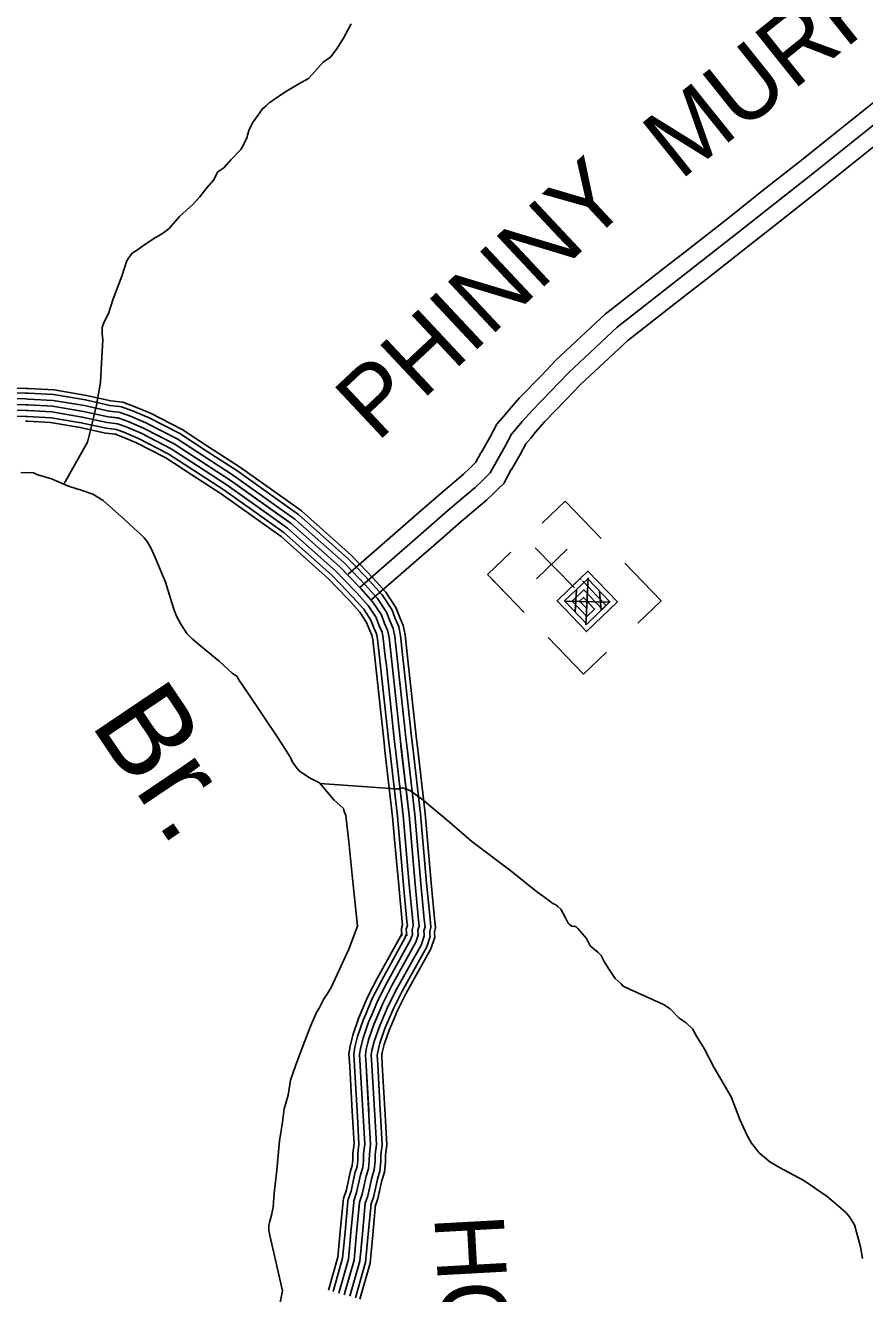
# Model space of a CAD drawing. Extents: x 1551132 to 1791609, y 378168 to 563823.
# Drawn here: x 1659703 to 1664184, y 426270 to 433041 of the extents above; entities that cross this region are included whole.
import ezdxf

# ---------------------------------------------------------------- set-up
doc = ezdxf.new("R2010")
doc.units = 0
for name, color, linetype in [('DESIGN - DRAINAGE - Bridges and Cross Drains Size Text', 7, 'Continuous'), ('DESIGN - ROW - Right-of-Way and Easement Labels', 7, 'Continuous'), ('DESIGN - TRANSPORTATION - Text', 7, 'Continuous'), ('DESIGN - UTILITIES - Cable (Underground) with Text', 7, 'Continuous'), ('SURVEY - CONTOURS - Index with Text', 7, 'Continuous'), ('SURVEY - PROPERTY - Owners', 7, 'Continuous')]:
    doc.layers.add(name, color=color, linetype=linetype)

msp = doc.modelspace()

# ---------------------------------------------------------------- linework, layer by layer
at = {"layer": 'DESIGN - TRANSPORTATION - Text'}
for points in [[(1659909.588, 430590.846), (1660034.993, 430815.902), (1660052.951, 430887.929), (1660083.842, 431013.89), (1660104.7, 431133.918), (1660109.459, 431238.038), (1660116.358, 431362.166), (1660112.592, 431394.242), (1660112.842, 431428.284), (1660123.025, 431454.252), (1660147.349, 431502.153), (1660169.866, 431576.105), (1660218.74, 431701.942), (1660235.089, 431751.901), (1660243.281, 431779.885), (1660253.405, 431797.844), (1660273.588, 431825.745), (1660301.688, 431843.57), (1660341.853, 431871.338), (1660392.052, 431905.03), (1660436.193, 431930.764), (1660470.35, 431956.565), (1660526.758, 432020.267), (1660599.164, 432085.86), (1660633.405, 432123.67), (1660671.729, 432173.479), (1660708.003, 432215.289), (1660730.295, 432259.198), (1660762.427, 432281.007), (1660802.71, 432324.783), (1660853.05, 432378.518), (1660867.208, 432402.452), (1660885.466, 432440.378), (1660895.749, 432480.362), (1660916.024, 432520.28), (1660944.281, 432560.14), (1660968.522, 432596.024), (1660988.622, 432611.908), (1661004.722, 432627.816), (1661026.796, 432641.683), (1661089.053, 432685.318), (1661163.301, 432728.861), (1661215.45, 432756.545), (1661263.807, 432812.288), (1661291.998, 432842.13), (1661334.189, 432873.89), (1661364.447, 432913.732), (1661400.846, 432973.567), (1661443.362, 433049.378)], [(1659678.535, 430653.997), (1659746.45, 430651.522), (1659770.358, 430641.339), (1659842.131, 430620.813), (1659933.746, 430580.12), (1660007.502, 430557.578), (1660063.318, 430539.161), (1660119.008, 430504.727), (1660232.155, 430403.799), (1660283.754, 430355.365), (1660315.512, 430327.106), (1660337.328, 430304.922), (1660353.169, 430284.788), (1660374.885, 430248.579), (1660396.51, 430200.361), (1660451.483, 430067.791), (1660494.432, 429929.295), (1660510.107, 429887.128), (1660531.79, 429846.918), (1660553.531, 429814.717), (1660565.372, 429794.608), (1660593.138, 429766.374), (1660648.745, 429719.923), (1660738.126, 429647.196), (1660785.75, 429602.804), (1660807.583, 429582.62), (1660833.424, 429564.419), (1660843.282, 429546.319), (1660888.756, 429479.909), (1661052.81, 429236.419), (1661117.984, 429131.816), (1661129.792, 429107.707), (1661149.583, 429081.532), (1661165.416, 429061.39), (1661183.316, 429049.248), (1661223.081, 429022.939), (1661272.838, 428996.555), (1661352.078, 428903.869), (1661381.861, 428877.627), (1661401.71, 428859.459), (1661405.585, 428843.409), (1661413.435, 428823.325), (1661430.393, 428683.005), (1661447.067, 428504.633)], [(1661276.072, 428992.771), (1661679.287, 428965.879), (1661697.27, 428965.754), (1661717.278, 428969.621), (1661733.228, 428965.504), (1661735.228, 428965.487), (1661759.127, 428955.312), (1661824.709, 428906.786), (1661967.697, 428787.624), (1662086.828, 428684.647), (1662295.464, 428526.968), (1662432.528, 428417.865), (1662496.126, 428371.356), (1662519.967, 428353.163), (1662535.9, 428345.038), (1662545.825, 428336.963), (1662561.708, 428322.829), (1662587.341, 428276.586), (1662601.124, 428248.452), (1662607.073, 428242.402), (1662620.99, 428232.285), (1662630.965, 428230.219), (1662634.973, 428232.194), (1662642.931, 428228.127), (1662652.864, 428220.052), (1662664.747, 428205.951), (1662698.421, 428165.659), (1662718.121, 428127.466), (1662728.054, 428119.382), (1662739.97, 428109.29), (1662759.828, 428093.123), (1662777.678, 428074.973), (1662793.427, 428042.822), (1662817.143, 428006.604), (1662852.709, 427952.278), (1662884.475, 427924.019), (1662894.375, 427911.935), (1662928.224, 427895.677), (1663109.445, 427814.3), (1663145.236, 427790.016), (1663192.834, 427741.614), (1663230.6, 427715.314), (1663264.333, 427683.038), (1663286.032, 427644.829), (1663327.506, 427578.443), (1663378.73, 427479.949), (1663471.478, 427321.078), (1663516.552, 427200.592), (1663555.884, 427114.198), (1663579.567, 427073.972), (1663621.141, 427021.612), (1663676.731, 426973.153), (1663728.463, 426942.752), (1663859.827, 426873.742), (1663983.082, 426788.765), (1664040.672, 426740.289), (1664084.346, 426701.938), (1664102.163, 426679.779), (1664129.829, 426637.528), (1664160.936, 426519.141), (1664172.111, 426457.29)], [(1661447.067, 428504.633), (1661476.008, 428231.776), (1661429.268, 428108.381), (1661335.878, 427904.734), (1661315.662, 427872.833), (1661295.454, 427840.924), (1661271.138, 427795.031), (1661256.98, 427771.097), (1661226.497, 427701.204), (1661183.74, 427591.343), (1661144.999, 427485.465), (1661118.475, 427409.538), (1661105.9, 427329.511), (1661085.4, 427257.551), (1661076.875, 427185.507), (1661060.167, 427085.471), (1661045.043, 426929.359), (1661032.16, 426807.272), (1661025.61, 426731.203), (1661017.31, 426689.202), (1661009.085, 426657.218), (1661002.935, 426635.226), (1661002.744, 426609.192), (1661008.535, 426581.108), (1661024.001, 426510.898), (1661053.067, 426386.519), (1661076.308, 426284.833)], [(1661076.308, 426284.833), (1660983.377, 425821.596), (1660931.436, 425683.818), (1660933.37, 425673.792), (1660948.894, 425601.565), (1660986.302, 425511.155), (1660990.91, 425500.588)]]:
    msp.add_lwpolyline(points, dxfattribs=at)
at = {"layer": 'DESIGN - UTILITIES - Cable (Underground) with Text'}
for p, q in [((1662462.01, 430383.033), (1662585.472, 430501.483)), ((1662777.58, 430301.289), (1662585.472, 430501.483)), ((1662171.011, 430109.835), (1662294.465, 430228.243)), ((1662596.209, 430244.655), (1662431.614, 430086.739)), ((1663096.619, 429968.617), (1662903.545, 430169.952)), ((1662171.011, 430109.835), (1662269.743, 430006.922)), ((1662188.735, 430091.31), (1662366.234, 429906.341)), ((1662973.157, 429850.209), (1663096.619, 429968.617)), ((1662493.967, 429773.112), (1662682.199, 429576.927)), ((1662682.199, 429576.927), (1662805.654, 429695.376))]:
    msp.add_line(p, q, dxfattribs=at)
for points in [[(1662424.97, 430252.044), (1662633.969, 430037.776)], [(1662620.678, 430051.409), (1662623.711, 430048.375), (1662705.992, 430127.358), (1662863.907, 429962.714), (1662699.304, 429804.84), (1662541.397, 429969.401), (1662664.851, 430087.842), (1662670.268, 430082.209)], [(1662677.176, 430075.001), (1662803.009, 429943.797), (1662700.145, 429845.105), (1662581.696, 429968.56), (1662705.159, 430087.009), (1662823.6, 429963.596), (1662782.468, 429924.08), (1662683.777, 430026.952), (1662622.045, 429967.769), (1662700.978, 429885.446), (1662742.119, 429924.913), (1662682.936, 429986.644), (1662662.345, 429966.894), (1662701.811, 429925.796)], [(1662645.586, 430028.401), (1662638.762, 429910.745)], [(1662706.875, 430091.451), (1662695.129, 429840.88)], [(1662582.179, 429967.551), (1662818.675, 429961.571)], [(1662768.6, 430018.195), (1662776.393, 429918.805)]]:
    msp.add_lwpolyline(points, dxfattribs=at)
at = {"layer": 'SURVEY - CONTOURS - Index with Text'}
for points in [[(1659705.093, 431102.192), (1659445.732, 431104.676), (1659199.663, 431090.375)], [(1659704.851, 431077.475), (1659446.332, 431079.95), (1659201.105, 431065.699)], [(1659704.56, 431046.474), (1659447.082, 431048.941), (1659202.896, 431034.757)], [(1660201.673, 430975.939), (1660149.991, 430981.806), (1660019.127, 431010.923), (1659850.981, 431038.957), (1659718.693, 431046.341), (1659704.535, 431046.474)], [(1660205.173, 431006.748), (1660155.124, 431012.424), (1660025.052, 431041.366), (1659854.406, 431069.817), (1659719.701, 431077.333), (1659704.818, 431077.475)], [(1660207.956, 431031.307), (1660159.207, 431036.833), (1660029.769, 431065.633), (1659857.131, 431094.417), (1659720.509, 431102.042), (1659705.051, 431102.192)], [(1659704.26, 431015.473), (1659447.832, 431017.932), (1659204.696, 431003.806)], [(1659703.96, 430984.473), (1659448.582, 430986.922), (1659206.496, 430972.855)], [(1661406.009, 426264.45), (1661458.199, 426448.738), (1661471.608, 426592.8), (1661487.224, 426758.871), (1661501.632, 426800.789), (1661522.556, 426896.716), (1661534.94, 426936.651), (1661539.348, 426978.66), (1661539.706, 427014.703), (1661546.206, 427066.712), (1661537.723, 427220.992), (1661522.34, 427487.49), (1661518.907, 427545.6), (1661523.182, 427573.592), (1661535.682, 427625.544), (1661564.473, 427707.371), (1661611.538, 427819.074), (1661660.454, 427914.726), (1661788.659, 428145.808), (1661801.026, 428183.742), (1661799.276, 428209.793), (1661805.492, 428231.76), (1661801.809, 428263.836), (1661783.701, 428456.266), (1661751.319, 428825.059), (1661705.203, 429220.011), (1661661.205, 429626.963), (1661644.647, 429773.317), (1661637.022, 429811.443), (1661621.389, 429847.635), (1661603.848, 429893.862), (1661558.541, 429962.388), (1661495.259, 430033.082), (1661382.461, 430150.318), (1661122.834, 430381.099), (1660797.25, 430612.513), (1660497.299, 430807.635), (1660334.186, 430891.295), (1660252.572, 430926.121), (1660202.773, 430944.622), (1660144.866, 430951.189), (1660013.211, 430980.481), (1659847.556, 431008.098), (1659717.684, 431015.348), (1659447.832, 431017.932)], [(1660194.69, 430914.338), (1660139.741, 430920.571), (1660007.294, 430950.038), (1659844.131, 430977.239), (1659716.676, 430984.356), (1659703.951, 430984.473)], [(1660198.181, 430945.138), (1660144.866, 430951.189), (1660013.211, 430980.481), (1659847.556, 431008.098), (1659717.684, 431015.348), (1659704.243, 431015.473)], [(1660656.854, 430740.817), (1660512.866, 430834.494), (1660347.361, 430919.38), (1660264.055, 430954.922), (1660210.031, 430974.998), (1660201.673, 430975.948)], [(1660673.762, 430766.809), (1660528.432, 430861.345), (1660360.536, 430947.464), (1660275.546, 430983.731), (1660217.289, 431005.373), (1660205.181, 431006.748)], [(1660687.236, 430787.526), (1660540.84, 430882.762), (1660371.036, 430969.856), (1660284.704, 431006.69), (1660223.072, 431029.591), (1660207.981, 431031.307)], [(1659703.668, 430953.472), (1659449.332, 430955.913), (1659208.288, 430941.913)], [(1660188.29, 430857.978), (1660130.358, 430864.553), (1659996.461, 430894.345), (1659837.873, 430920.779), (1659714.834, 430927.654), (1659703.426, 430927.754)], [(1660191.19, 430883.529), (1660134.608, 430889.954), (1660001.369, 430919.596), (1659840.706, 430946.38), (1659715.668, 430953.363), (1659703.668, 430953.472)], [(1660623.055, 430688.849), (1660481.733, 430780.776), (1660321.012, 430863.211), (1660241.089, 430897.321), (1660195.515, 430914.246), (1660194.656, 430914.346)], [(1660639.954, 430714.833), (1660497.299, 430807.635), (1660334.186, 430891.295), (1660252.572, 430926.121), (1660202.773, 430944.622), (1660198.165, 430945.147)], [(1660592.122, 430641.306), (1660453.25, 430731.641), (1660296.912, 430811.827), (1660220.072, 430844.619), (1660182.24, 430858.678)], [(1660606.147, 430662.856), (1660466.167, 430753.925), (1660307.837, 430835.127), (1660229.597, 430868.511), (1660188.257, 430883.87)], [(1661102.06, 430502.252), (1660846.033, 430684.232), (1660687.22, 430787.543)], [(1661051.828, 430431.567), (1660797.25, 430612.513), (1660639.938, 430714.849)], [(1661069.786, 430456.834), (1660814.692, 430638.156), (1660656.837, 430740.833)], [(1661087.744, 430482.102), (1660832.125, 430663.79), (1660673.745, 430766.826)], [(1661001.012, 430360.065), (1660747.91, 430539.97), (1660592.105, 430641.322)], [(1661015.912, 430381.032), (1660762.376, 430561.237), (1660606.13, 430662.873)], [(1661033.87, 430406.3), (1660779.809, 430586.871), (1660623.038, 430688.865)], [(1661490.351, 430163.252), (1661442.602, 430212.887), (1661176.916, 430449.051), (1661102.043, 430502.261)], [(1661427.869, 430103.125), (1661382.461, 430150.318), (1661122.834, 430381.099), (1661051.811, 430431.575)], [(1661450.21, 430124.618), (1661403.961, 430172.686), (1661142.167, 430405.391), (1661069.769, 430456.843)], [(1661472.543, 430146.118), (1661425.46, 430195.053), (1661161.5, 430429.684), (1661087.727, 430482.118)], [(1661383.195, 430060.133), (1661339.462, 430105.584), (1661084.169, 430332.515), (1661015.895, 430381.032)], [(1661405.528, 430081.633), (1661360.962, 430127.951), (1661103.501, 430356.807), (1661033.853, 430406.308)], [(1661364.662, 430042.307), (1661321.63, 430087.033), (1661068.127, 430312.364), (1661000.996, 430360.074)], [(1661741.828, 429685.673), (1661730.395, 429786.717), (1661720.253, 429837.427), (1661701.771, 429880.228), (1661681.496, 429933.646), (1661627.381, 430015.507), (1661558.824, 430092.083), (1661490.351, 430163.26)], [(1661655.663, 429675.923), (1661644.647, 429773.317), (1661637.022, 429811.443), (1661621.389, 429847.635), (1661603.848, 429893.862), (1661558.541, 429962.388), (1661495.259, 430033.082), (1661427.86, 430103.134)], [(1661686.462, 429679.406), (1661675.304, 429778.109), (1661666.78, 429820.735), (1661650.122, 429859.286), (1661631.606, 429908.087), (1661583.148, 429981.381), (1661517.983, 430054.174), (1661450.202, 430124.626)], [(1661717.27, 429682.889), (1661705.954, 429782.9), (1661696.529, 429830.018), (1661678.863, 429870.936), (1661659.363, 429922.304), (1661607.756, 430000.364), (1661540.708, 430075.266), (1661472.534, 430146.118)], [(1661568.507, 429666.064), (1661557.907, 429759.758), (1661552.824, 429785.159), (1661540.083, 429814.668), (1661525.3, 429853.619), (1661488.909, 429908.662), (1661430.96, 429973.397), (1661364.654, 430042.315)], [(1661594.056, 429668.956), (1661583.34, 429763.733), (1661577.515, 429792.867), (1661563.915, 429824.335), (1661548.332, 429865.419), (1661509.325, 429924.412), (1661449.81, 429990.897), (1661383.186, 430060.149)], [(1661624.864, 429672.439), (1661613.989, 429768.525), (1661607.264, 429802.151), (1661592.656, 429835.985), (1661576.09, 429879.636), (1661533.933, 429943.396), (1661472.534, 430011.99), (1661405.519, 430081.641)], [(1661622.88, 429168.718), (1661618.039, 429210.21), (1661574.023, 429617.313), (1661568.507, 429666.081)], [(1661648.421, 429171.693), (1661643.597, 429213.085), (1661599.581, 429620.146), (1661594.056, 429668.964)], [(1661679.212, 429175.293), (1661674.396, 429216.544), (1661630.397, 429623.555), (1661624.864, 429672.456)], [(1661710.003, 429178.885), (1661705.203, 429220.011), (1661661.205, 429626.963), (1661655.663, 429675.939)], [(1661740.794, 429182.476), (1661736.011, 429223.477), (1661692.012, 429630.371), (1661686.462, 429679.423)], [(1661771.585, 429186.076), (1661766.81, 429226.936), (1661722.828, 429633.78), (1661717.27, 429682.914)], [(1661796.135, 429188.935), (1661791.376, 429229.703), (1661747.394, 429636.497), (1661741.828, 429685.69)], [(1661676.512, 428674.171), (1661664.054, 428816.133), (1661622.88, 429168.726)], [(1661702.137, 428676.421), (1661689.637, 428818.75), (1661648.421, 429171.709)], [(1661733.011, 428679.138), (1661720.478, 428821.9), (1661679.212, 429175.309)], [(1661763.893, 428681.847), (1661751.319, 428825.059), (1661710.003, 429178.901)], [(1661794.776, 428684.555), (1661782.16, 428828.217), (1661740.794, 429182.493)], [(1661825.65, 428687.272), (1661813.001, 428831.367), (1661771.585, 429186.093)], [(1661850.275, 428689.43), (1661837.592, 428833.884), (1661796.135, 429188.96)], [(1661713.444, 428178.825), (1661710.744, 428219.068), (1661716.369, 428238.968), (1661714.561, 428254.719), (1661696.345, 428448.324), (1661676.512, 428674.188)], [(1661739.102, 428180.55), (1661736.694, 428216.351), (1661742.502, 428236.86), (1661740.144, 428257.394), (1661721.961, 428450.649), (1661702.137, 428676.438)], [(1661770.026, 428182.625), (1661767.985, 428213.068), (1661773.993, 428234.31), (1661770.976, 428260.611), (1661752.827, 428453.457), (1661733.011, 428679.155)], [(1661800.959, 428184.7), (1661799.276, 428209.793), (1661805.492, 428231.76), (1661801.809, 428263.836), (1661783.701, 428456.266), (1661763.893, 428681.863)], [(1661831.892, 428186.775), (1661830.567, 428206.518), (1661836.991, 428229.21), (1661832.642, 428267.061), (1661814.575, 428459.074), (1661794.776, 428684.572)], [(1661862.816, 428188.85), (1661861.858, 428203.234), (1661868.482, 428226.66), (1661863.474, 428270.278), (1661845.441, 428461.883), (1661825.65, 428687.288)], [(1661887.482, 428190.509), (1661886.799, 428200.617), (1661893.598, 428224.635), (1661888.057, 428272.844), (1661870.057, 428464.124), (1661850.275, 428689.447)], [(1661496.758, 427772.556), (1661531.965, 427856.125), (1661583.031, 427955.986), (1661707.878, 428181), (1661712.353, 428194.742)], [(1661520.457, 427762.572), (1661555.298, 427845.266), (1661605.73, 427943.894), (1661731.561, 428170.683), (1661738.352, 428191.517)], [(1661549.023, 427750.53), (1661583.414, 427832.166), (1661633.096, 427929.31), (1661760.11, 428158.25), (1661769.685, 428187.634)], [(1661577.589, 427738.497), (1661611.538, 427819.074), (1661660.454, 427914.726), (1661788.659, 428145.808), (1661801.026, 428183.742), (1661800.959, 428184.717)], [(1661606.155, 427726.463), (1661639.663, 427805.982), (1661687.811, 427900.143), (1661817.209, 428133.366), (1661832.367, 428179.85), (1661831.883, 428186.834)], [(1661634.721, 427714.421), (1661667.779, 427792.882), (1661715.177, 427885.559), (1661845.758, 428120.932), (1661863.699, 428175.967), (1661862.816, 428188.95)], [(1661657.504, 427704.821), (1661690.203, 427782.448), (1661736.994, 427873.934), (1661868.524, 428111.015), (1661888.69, 428172.867), (1661887.474, 428190.634)], [(1661448.567, 427243.325), (1661434.776, 427482.373), (1661430.801, 427549.683), (1661437.034, 427590.501), (1661451.45, 427650.428), (1661482.616, 427738.988), (1661496.766, 427772.581)], [(1661474.241, 427244.8), (1661460.45, 427483.873), (1661456.633, 427548.483), (1661462.292, 427585.543), (1661476.141, 427643.136), (1661506.616, 427729.721), (1661520.465, 427762.597)], [(1661505.19, 427246.592), (1661491.391, 427485.682), (1661487.766, 427547.042), (1661492.733, 427579.568), (1661505.916, 427634.336), (1661535.54, 427718.546), (1661549.031, 427750.555)], [(1661536.14, 427248.376), (1661522.34, 427487.49), (1661518.907, 427545.6), (1661523.182, 427573.592), (1661535.682, 427625.544), (1661564.473, 427707.371), (1661577.597, 427738.513)], [(1661567.089, 427250.159), (1661553.289, 427489.299), (1661550.048, 427544.158), (1661553.631, 427567.617), (1661565.448, 427616.752), (1661593.405, 427696.196), (1661606.163, 427726.471)], [(1661598.038, 427251.951), (1661584.23, 427491.107), (1661581.18, 427542.717), (1661584.072, 427561.642), (1661595.222, 427607.952), (1661622.33, 427685.02), (1661634.729, 427714.429)], [(1661622.713, 427253.376), (1661608.905, 427492.549), (1661606.013, 427541.567), (1661608.346, 427556.875), (1661618.955, 427600.943), (1661645.396, 427676.112), (1661657.504, 427704.838)], [(1661517.74, 426752.296), (1661531.531, 426792.422), (1661552.556, 426888.808), (1661565.447, 426930.384), (1661570.33, 426976.885), (1661570.689, 427012.619), (1661577.314, 427065.629), (1661568.672, 427222.733), (1661567.089, 427250.184)], [(1661548.264, 426745.721), (1661561.439, 426784.047), (1661582.563, 426880.899), (1661595.963, 426924.117), (1661601.313, 426975.11), (1661601.663, 427010.536), (1661608.413, 427064.554), (1661599.622, 427224.483), (1661598.038, 427251.967)], [(1661572.597, 426740.471), (1661585.28, 426777.372), (1661606.488, 426874.591), (1661620.288, 426919.117), (1661626.021, 426973.693), (1661626.371, 427008.878), (1661633.221, 427063.696), (1661624.304, 427225.875), (1661622.713, 427253.392)], [(1661399.609, 426764.029), (1661400.868, 426777.48), (1661417.017, 426824.473), (1661437.658, 426919.092), (1661448.608, 426954.393), (1661451.675, 426983.685), (1661452.05, 427020.595), (1661458.191, 427069.771), (1661450.15, 427216.05), (1661448.575, 427243.334)], [(1661425.209, 426761.629), (1661426.184, 426772.021), (1661441.825, 426817.531), (1661462.55, 426912.533), (1661473.916, 426949.184), (1661477.383, 426982.21), (1661477.749, 427018.87), (1661483.999, 427068.871), (1661475.824, 427217.5), (1661474.241, 427244.817)], [(1661456.075, 426758.738), (1661456.708, 426765.446), (1661471.733, 426809.156), (1661492.557, 426904.625), (1661504.432, 426942.918), (1661508.365, 426980.435), (1661508.724, 427016.786), (1661515.098, 427067.796), (1661506.774, 427219.25), (1661505.19, 427246.6)], [(1661486.941, 426755.846), (1661487.224, 426758.871), (1661501.632, 426800.789), (1661522.556, 426896.716), (1661534.94, 426936.651), (1661539.348, 426978.66), (1661539.706, 427014.703), (1661546.206, 427066.712), (1661537.723, 427220.992), (1661536.14, 427248.392)], [(1661321.611, 426288.35), (1661371.61, 426464.888), (1661384.276, 426600.967), (1661399.609, 426764.071)], [(1661346.36, 426281.342), (1661396.993, 426460.155), (1661409.876, 426598.575), (1661425.217, 426761.671)], [(1661376.185, 426272.9), (1661427.6, 426454.446), (1661440.742, 426595.692), (1661456.075, 426758.763)], [(1661406.009, 426264.45), (1661458.199, 426448.738), (1661471.608, 426592.8), (1661486.941, 426755.863)], [(1661435.833, 426255.999), (1661488.799, 426443.029), (1661502.473, 426589.908), (1661517.807, 426752.963)], [(1661465.657, 426247.558), (1661519.406, 426437.321), (1661533.339, 426587.025), (1661548.664, 426750.054)], [(1661489.44, 426240.816), (1661543.806, 426432.771), (1661557.947, 426584.725), (1661573.272, 426747.746)]]:
    msp.add_lwpolyline(points, dxfattribs=at)
at = {"layer": 'SURVEY - PROPERTY - Owners'}
for points in [[(1661488.409, 430040.207), (1661971.231, 430461.102), (1662104.27, 430573.98), (1662142.411, 430609.939), (1662161.835, 430629.365), (1662184.993, 430651.307), (1662217.584, 430713.075), (1662264.858, 430794.919), (1662298.965, 430858.487), (1662331.323, 430896.23), (1662355.597, 430926.039), (1662410.179, 430987.599), (1662602.033, 431186.021), (1662862.294, 431429.861), (1663158.429, 431661.334), (1663510.954, 431936.324), (1663913.887, 432254.891), (1664697.669, 432882.233)], [(1661426.452, 430111.284), (1661803.343, 430439.834), (1661909.749, 430532.595), (1662041.388, 430644.282), (1662076.72, 430677.599), (1662096.062, 430696.941), (1662108.853, 430709.067), (1662135.027, 430758.66), (1662137.611, 430763.143), (1662182.476, 430840.803), (1662220.717, 430912.089), (1662258.966, 430956.698), (1662283.732, 430987.116), (1662340.981, 431051.684), (1662457.978, 431172.687), (1662535.868, 431253.239), (1662800.904, 431501.554), (1662830.728, 431524.872), (1663100.397, 431735.652), (1663224.836, 431832.722), (1663452.722, 432010.485), (1663617.735, 432140.947), (1663855.188, 432328.685), (1664008.784, 432451.622), (1664399.142, 432764.063)], [(1661548.008, 429971.83), (1661924.899, 430300.381), (1662030.38, 430392.325), (1662164.76, 430506.345), (1662205.601, 430544.854), (1662225.109, 430564.355), (1662258.233, 430595.747), (1662297.007, 430669.224), (1662297.815, 430670.632), (1662344.114, 430750.776), (1662374.239, 430806.919), (1662400.93, 430838.062), (1662424.729, 430867.279), (1662476.753, 430925.956), (1662590.967, 431044.084), (1662665.682, 431121.353), (1662921.351, 431360.892), (1662944.659, 431379.11), (1663214.253, 431589.832), (1663338.616, 431686.843), (1663566.978, 431864.981), (1663732.466, 431995.818), (1663970.352, 432183.898), (1664124.382, 432307.185), (1664514.739, 432619.626)]]:
    msp.add_lwpolyline(points, dxfattribs=at)

# ---------------------------------------------------------------- texts
at = {"layer": 'DESIGN - DRAINAGE - Bridges and Cross Drains Size Text'}
msp.add_text('Br.', height=475.0049, rotation=303.9706389, dxfattribs=at).set_placement((1660045.148, 429314.584))
at = {"layer": 'DESIGN - ROW - Right-of-Way and Easement Labels'}
for s, height, rotation, p in [('MURPHY', 369.9987, 38.6737306, (1663198.837, 432209.39)), ('PHINNY', 370.0001, 43.13445, (1661581.032, 430811.119)), ('HOLLOW', 370.0096, 273.1464056, (1661886.015, 426684.069)), ('ORCHARD', 370.0061, 63.0558139, (1663525.291, 423968.832))]:
    msp.add_text(s, height=height, rotation=rotation, dxfattribs=at).set_placement(p)

doc.saveas('drawing.dxf')
